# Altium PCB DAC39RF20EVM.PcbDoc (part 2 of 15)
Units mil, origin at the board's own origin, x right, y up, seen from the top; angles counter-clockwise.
Board outline 6200 x 2716.54 mil, 16 copper layers (Top Layer, L2 GND, L3 PWR, L4 GND, L5 PWR, L6 GND, L7 SIG, L8 GND, L9 GND, L10 SIG, L11 GND, L12 PWR, L13 GND, L14 PWR, L15 GND, Bottom Layer), stack 76.97 mil thick; 766 components, 495 nets, 3414 pads, 2373 vias.
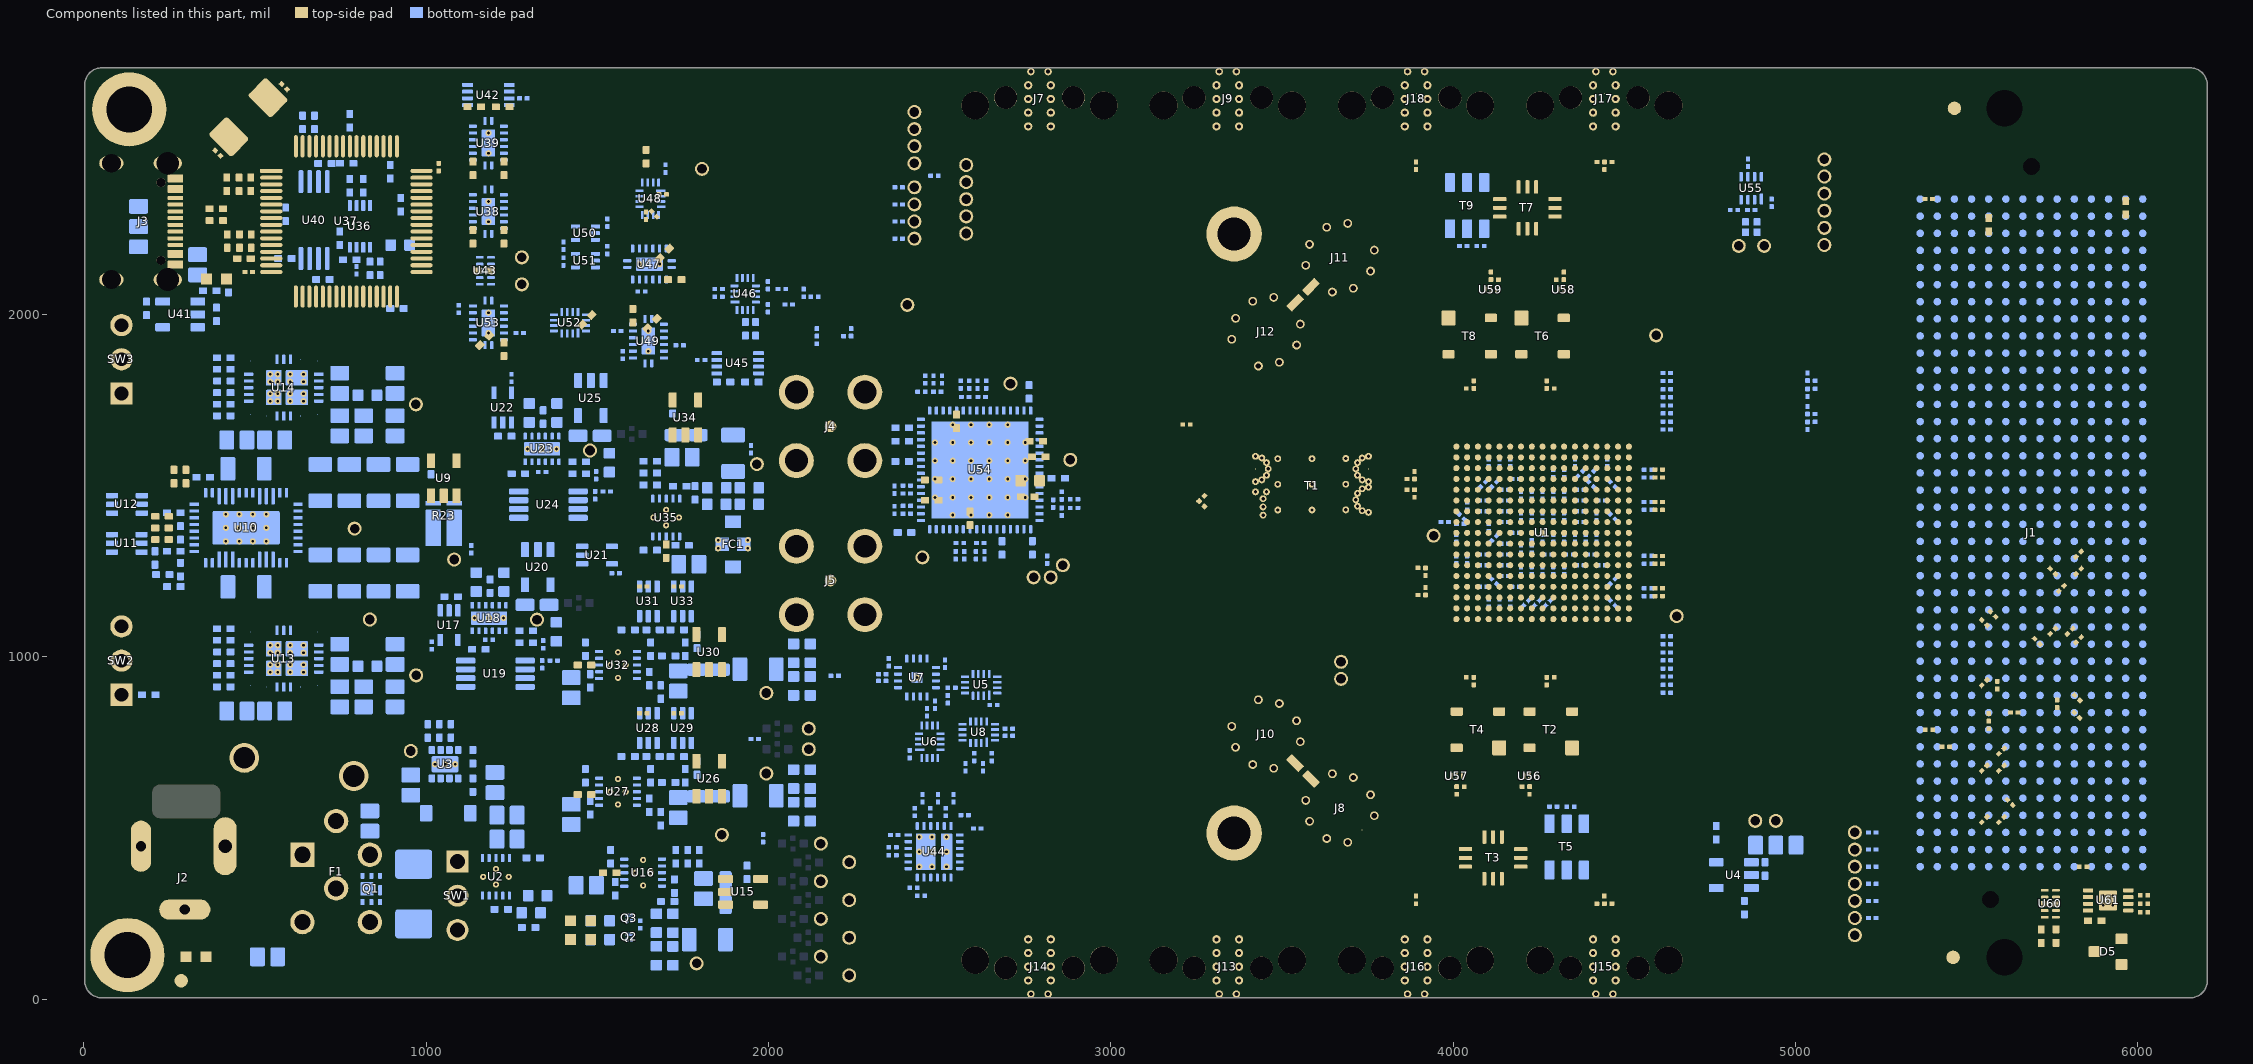
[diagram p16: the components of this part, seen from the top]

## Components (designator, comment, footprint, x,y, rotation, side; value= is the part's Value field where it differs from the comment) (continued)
C314 "GRM033Z71C104KE14D" 0201_cap 4150.76,1235.98 r0 bottom value="0.1 uF"
C315 "GRT155R71E104KE01J" 0402L_cap#1 5760.47,184.11 r90 top value="0.1 uF"
C316 "GRT155R71E104KE01J" 0402L_cap#1 5874.08,228.79 r180 top value="0.1 uF"
D1 "LTST-C191TGKT" LED_LTST-C190-Green 327.74,123.65 r0 top
D2 "SMBJ15CA" SMBJ15CA 963.6,306.98 r90 bottom
D3 "MBR130T1G" SOD-123 1064.36,543.16 r180 bottom
D4 "LTST-C191TGKT" LED_LTST-C190-Green 387.59,2103.8 r0 top
D5 "SDM40E20LC-7" SOT-323-DIO 5912.59,138.8 r180 top
D6 "LTST-C190KRKT" LED_LTST-C190-Red 1451.22,174.11 r180 top
D7 "LTST-C190KRKT" LED_LTST-C190-Red 1451.22,229.11 r180 top
F1 "BNX002-11" FIL_BNX002-11 737.07,323.38 r90 top
FB1 "BLE18PS080SN1D" 0603L 828.49,972.43 r0 bottom value=-
FB2 "BLE18PS080SN1D" 0603L 828.49,1763.95 r0 bottom value=-
FB3 "BLM31KN601SN1L" 1206L 1821.49,174.11 r180 bottom value=-
FB4 "BLM31KN601SN1L" 1206L 1969.67,593.85 r0 bottom value=-
FB5 "BLM31KN601SN1L" 1206L 1969.67,963.85 r0 bottom value=-
FB6 "BLM31KN601SN1L" 1206L 1896.28,1594.5 r270 bottom value=-
FB7 "NFZ15SG151SN11D" 0402L_cap#1 418.96,2214.36 r90 top value=-
FB8 "NFZ15SG151SN11D" 0402L_cap#1 417.59,2379.88 r270 top value=-
FC1 "dcp00001" NFM31PC 1896.28,1328.65 r270 bottom value=27uF
FID1 "Fiducial Mark" Fiducial10-20 284.47,53.8 r90 top
FID2 "Fiducial Mark" Fiducial10-20 5460.01,122.07 r90 top
FID3 "Fiducial Mark" Fiducial10-20 5464.01,2602.07 r90 top
H1 "CBTS130A" cbts130a 132.59,2598.8 r0 top locked
H3 "CBTS130A" cbts130a 127.59,128.8 r0 top
H5 "1797A" Keystone_1797B 3360,2235 r0 top
H6 "1797A" Keystone_1797B 3360,485 r0 top
J1 "ASP-184330-01" Samtec_ASP-184330-01 5689.01,1362.07 r90 bottom locked
J2 "RAPC722X" RAPC722X 167.02,446.8 r0 top
J3 "USB4105-GF-A" FP-USB4105-GF-A_CONN_USB_9MM58_7MM53-MFG 126.41,2271.61 r270 top
J4 "132134-15" FP-132134-15_CONN_SMA_JACK-MFG 2181.22,1672.88 r90 top
J5 "132134-15" FP-132134-15_CONN_SMA_JACK-MFG 2181.22,1222.88 r0 top
J7 "HK-LR-SR2(11)" HiRose-HK-LR-SR2-SWM1092-04A-MicroStirp-6mil-Female-Backdrill 2791.51,2720.34 r270 top
J8 "0853050232" Molex_0853050232 3584.5,643.16 r45 top
J9 "HK-LR-SR2(11)" HiRose-HK-LR-SR2-SWM1092-04A-MicroStirp-6mil-Female-Backdrill 3341.51,2720.34 r270 top
J10 "0853050232" Molex_0853050232 3538.14,689.52 r225 top
J11 "0853050232" Molex_0853050232 3584.45,2080.73 r135 top
J12 "0853050232" Molex_0853050232 3538.19,2034.47 r315 top
J13 "HK-LR-SR2(11)" HiRose-HK-LR-SR2-SWM1092-04A-MicroStirp-6mil-Female-Backdrill 3341.51,3.8 r90 top
J14 "HK-LR-SR2(11)" HiRose-HK-LR-SR2-SWM1092-04A-MicroStirp-6mil-Female-Backdrill 2791.51,3.8 r90 top
J15 "HK-LR-SR2(11)" HiRose-HK-LR-SR2-SWM1092-04A-MicroStirp-6mil-Female-Backdrill 4441.51,3.8 r90 top
J16 "HK-LR-SR2(11)" HiRose-HK-LR-SR2-SWM1092-04A-MicroStirp-6mil-Female-Backdrill 3891.51,3.8 r90 top
J17 "HK-LR-SR2(11)" HiRose-HK-LR-SR2-SWM1092-04A-MicroStirp-6mil-Female-Backdrill 4441.51,2720.34 r270 top
J18 "HK-LR-SR2(11)" HiRose-HK-LR-SR2-SWM1092-04A-MicroStirp-6mil-Female-Backdrill 3891.51,2720.34 r270 top
LBL1 "THT-14-423-10" Label_650x200 4941.3,816.41 r180 top
LOGO1 "CAUTION HOT SURFACE" IEC_HotSurface_Small 4777.61,1803.8 r0 top
Logo2 "FCC disclaimer" FCC_disclaimer 3657.85,1904.24 r180 bottom
Logo3 "ESD Overlay" ESD_Overlay_Small 4515,1760 r0 top
Logo4 "WEEE" WEEE_Minimum 1952.61,2423.8 r180 bottom
LOGO5 "CE Mark" CE_Mark_5mm 2895,2080 r180 bottom
Logo6 "Texas Instruments" TI_Stacked_Overlay_Small_Vertical 5642.61,1848.8 r270 top
Logo7 "FDL Logo" FDL_Small 1176.93,870.94 r0 top
Logo8 "Texas Instruments" TI_Symbol_Overlay_Medium 2588.66,694.83 r0 top
PP1 "Probe Point" ProbePoint_TH_40mil 955.09,724.79 r0 top
PP2 "Probe Point" ProbePoint_TH_40mil 4942.16,520.76 r90 top
PP3 "Probe Point" ProbePoint_TH_40mil 4882.16,520.76 r90 top
PP4 "Probe Point" ProbePoint_TH_40mil 2449.61,1290.17 r0 top
PP5 "Probe Point" ProbePoint_TH_40mil 5084.05,2202.9 r0 top
PP6 "Probe Point" ProbePoint_TH_40mil 5173.01,186.94 r0 top
PP7 "Probe Point" ProbePoint_TH_40mil 1805.78,2425.07 r0 top
PP8 "Probe Point" ProbePoint_TH_40mil 1863.97,479.87 r0 top
PP9 "Probe Point" ProbePoint_TH_40mil 835.49,1109 r0 top
PP10 "Probe Point" ProbePoint_TH_40mil 790.91,1374.53 r0 bottom
PP11 "Probe Point" ProbePoint_TH_40mil 1081.93,1284.07 r0 bottom
PP12 "Probe Point" ProbePoint_TH_40mil 970.86,945.8 r0 top
PP13 "Probe Point" ProbePoint_TH_40mil 970.09,1737.32 r0 top
PP14 "Probe Point" ProbePoint_TH_40mil 1789.86,104.37 r180 bottom
PP15 "Probe Point" ProbePoint_TH_40mil 2152.86,454.37 r0 top
PP16 "Probe Point" ProbePoint_TH_40mil 2152.86,124.37 r0 top
PP17 "Probe Point" ProbePoint_TH_40mil 2235.74,69.37 r0 top
PP18 "Probe Point" ProbePoint_TH_40mil 2152.86,234.37 r0 top
PP19 "Probe Point" ProbePoint_TH_40mil 2235.74,289.37 r0 top
PP20 "Probe Point" ProbePoint_TH_40mil 2152.86,344.37 r0 top
PP21 "Probe Point" ProbePoint_TH_40mil 2235.74,400.14 r0 top
PP22 "Probe Point" ProbePoint_TH_40mil 2235.74,179.37 r0 top
PP23 "Probe Point" ProbePoint_TH_40mil 1323.69,1108.44 r270 bottom
PP24 "Probe Point" ProbePoint_TH_40mil 1478.5,1602.46 r90 top
PP25 "Probe Point" ProbePoint_TH_40mil 1993.58,659.19 r180 bottom
PP26 "Probe Point" ProbePoint_TH_40mil 2117.52,730.04 r270 bottom
PP27 "Probe Point" ProbePoint_TH_40mil 2117.52,790.04 r180 bottom
PP28 "Probe Point" ProbePoint_TH_40mil 1993.58,894.19 r0 bottom
PP29 "Probe Point" ProbePoint_TH_40mil 1966.02,1562.87 r270 bottom
PP30 "Probe Point" ProbePoint_TH_40mil 1279.44,2088.03 r0 top
PP31 "Probe Point" ProbePoint_TH_40mil 1279.44,2166.77 r0 top
PP32 "Probe Point" ProbePoint_TH_40mil 2824.32,1232.14 r0 top
PP33 "Probe Point" ProbePoint_TH_40mil 2774.32,1232.14 r0 top
PP34 "Probe Point" ProbePoint_TH_40mil 2706.77,1798.03 r0 top
PP35 "Probe Point" ProbePoint_TH_40mil 2859.68,1267.5 r0 top
PP36 "Probe Point" ProbePoint_TH_40mil 5084.05,2402.9 r0 top
PP37 "Probe Point" ProbePoint_TH_40mil 5084.05,2352.9 r0 top
PP38 "Probe Point" ProbePoint_TH_40mil 5084.05,2452.9 r0 top
PP39 "Probe Point" ProbePoint_TH_40mil 5084.05,2252.9 r0 top
PP40 "Probe Point" ProbePoint_TH_40mil 2405.59,2027.82 r90 top
PP41 "Probe Point" ProbePoint_TH_40mil 5084.05,2302.9 r0 top
PP42 "Probe Point" ProbePoint_TH_40mil 2426.12,2371.38 r0 top
PP43 "Probe Point" ProbePoint_TH_40mil 2426.12,2221.38 r0 top
PP44 "Probe Point" ProbePoint_TH_40mil 2426.12,2321.38 r0 top
PP45 "Probe Point" ProbePoint_TH_40mil 2426.12,2271.38 r0 top
PP46 "Probe Point" ProbePoint_TH_40mil 2881.41,1575.36 r180 bottom
PP47 "Probe Point" ProbePoint_TH_40mil 3672.29,935.47 r0 top
PP48 "Probe Point" ProbePoint_TH_40mil 5173.01,486.94 r180 top
PP49 "Probe Point" ProbePoint_TH_40mil 5173.01,236.94 r180 top
PP50 "Probe Point" ProbePoint_TH_40mil 5173.01,286.94 r180 top
PP51 "Probe Point" ProbePoint_TH_40mil 5173.01,336.94 r180 top
PP52 "Probe Point" ProbePoint_TH_40mil 5173.01,386.94 r180 top
PP53 "Probe Point" ProbePoint_TH_40mil 5173.01,436.94 r180 top
PP54 "Probe Point" ProbePoint_TH_40mil 3672.29,985.47 r0 top
PP55 "Probe Point" ProbePoint_TH_40mil 4908.08,2200.21 r90 top
PP56 "Probe Point" ProbePoint_TH_40mil 2577.51,2436.45 r0 top
PP57 "Probe Point" ProbePoint_TH_40mil 3942.61,1353.8 r0 top
PP58 "Probe Point" ProbePoint_TH_40mil 4592.61,1938.8 r0 top
PP59 "Probe Point" ProbePoint_TH_40mil 2577.51,2386.45 r0 top
PP60 "Probe Point" ProbePoint_TH_40mil 4834.03,2200.21 r90 top
PP61 "Probe Point" ProbePoint_TH_40mil 2577.51,2336.45 r0 top
PP62 "Probe Point" ProbePoint_TH_40mil 4652.61,1118.8 r0 top
PP63 "Probe Point" ProbePoint_TH_40mil 2577.51,2236.45 r0 top
PP64 "Probe Point" ProbePoint_TH_40mil 2577.51,2286.45 r0 top
PP65 "Probe Point" ProbePoint_TH_40mil 2426.12,2591.38 r0 top
PP66 "Probe Point" ProbePoint_TH_40mil 2426.12,2491.38 r0 top
PP67 "Probe Point" ProbePoint_TH_40mil 2426.12,2441.38 r0 top
PP68 "Probe Point" ProbePoint_TH_40mil 2426.12,2541.38 r0 top
Q1 "CSD15571Q2" DQK0006C 839.83,321.96 r270 bottom
Q2 "CSD25480F3" YJM0003A 1592.76,181 r90 bottom value=-20V
Q3 "CSD25480F3" YJM0003A 1592.76,236 r90 bottom value=-20V
R1 "ERJ-2RKF1004X" 0402L#1 1219.35,262.2 r180 bottom value="1 MΩ"
R2 "ERJ-2RKF7682X" 0402L#1 1312.87,412.44 r180 bottom value="76.8 kΩ"
R3 "ERJ-6ENF4701V" 0805L 536.79,123.65 r180 bottom value="4.7 kΩ"
R4 "ERJ-2RKF1623X" 0402L#1 1299.22,209.42 r180 bottom value="162 kΩ"
R5 "ERJ-2RKF1002X" 0402L#1 1071.89,783.31 r90 bottom value="10 kΩ"
R6 "ERJ-6GEY0R00V" 0805L 4912.63,449.74 r180 bottom value="0 Ω"
R7 "ERJ-6GEY0R00V" 0805L 4971.69,449.74 r180 bottom value="0 Ω"
R8 "ERJ-2RKF1002X" 0402L#1 1136.48,625.27 r270 bottom value="10 kΩ"
R9 "ERJ-2RKF1002X" 0402L#1 4850.49,267.45 r270 bottom value="10 kΩ"
R10 "ERA-2AEB3742X" 0402L#1 1038.3,783.31 r90 bottom value="37.4 kΩ"
R11 "ERJ-2RKF1202X" 0402L#1 1004.7,783.31 r270 bottom value="12 kΩ"
R12 "ERJ-1GNF1000C" 0201#1 2534.65,909.89 r180 bottom value="100 Ω"
R13 "ERJ-1GNF1002C" 0201#1 2626.71,677.07 r270 bottom value="10 kΩ"
R14 "ERJ-1GNF1002C" 0201#1 2600.96,707.07 r270 bottom value="10 kΩ"
R15 "ERJ-1GNF1002C" 0201#1 2575.21,677.07 r270 bottom value="10 kΩ"
R16 "ERJ-1GNF1000C" 0201#1 2463.04,838.27 r90 bottom value="100 Ω"
R17 "ERJ-1GNF1002C" 0201#1 2351.39,983.97 r90 bottom value="10 kΩ"
R18 "ERJ-1GNF1002C" 0201#1 2515.63,979.97 r90 bottom value="10 kΩ"
R19 "ERJ-1GNF1002C" 0201#1 2652.46,707.07 r270 bottom value="10 kΩ"
R20 "ERJ-2RKF1002X" 0402L#1 349.09,1524.51 r180 bottom value="10 kΩ"
R21 "ERJ-2RKF1003X" 0402L#1 298.22,1526.56 r90 top value="100 kΩ"
R22 "ERJ-1GNF1000C" 0201#1 1131.81,1314.23 r270 bottom value="100 Ω"
R23 "KRL3216T4A-M-R005-F-T1" FP-KRL3216T4A-M-R005-F-T1_1206-MFG 1051.42,1389.39 r180 bottom
R24 "ERA-2APB2551X" 0402L#1 228.46,1342.34 r180 top value="2.55 kΩ"
R25 "ERJ-2RKF1402X" 0402L#1 263.22,1526.57 r270 top value="14 kΩ"
R26 "ERJ-2RKF1002X" 0402L#1 282.52,1254.54 r90 bottom value="10 kΩ"
R27 "ERJ-2RKF1072X" 0402L#1 262.83,1205.23 r0 bottom value="10.7 kΩ"
R28 "ERJ-2RKF1742X" 0402L#1 230.83,1240.23 r0 bottom value="17.4 kΩ"
R29 "ERA-2ARB222X" 0402L#1 228.46,1376.34 r0 top value="2.2 kΩ"
R30 "ERA-2ARB1692X" 0402L#1 282.52,1362.03 r90 bottom value="16.9 kΩ"
R31 "ERJ-PA2F1004X" 0402L#1 207.78,1288.66 r270 bottom value="1 MΩ"
R32 "ERA-2APB223X" 0402L#1 228.46,1410.34 r0 top value="22 kΩ"
R33 "ERJ-2RKF1002X" 0402L#1 409.06,912.11 r180 bottom value="10 kΩ"
R34 "ERJ-2RKF1002X" 0402L#1 409.06,1082.11 r180 bottom value="10 kΩ"
R35 "ERA-2AEB9311X" 0402L#1 409.06,980.11 r180 bottom value="9.31 kΩ"
R36 "ERJ-2RKF8062X" 0402L#1 409.06,1048.11 r0 bottom value="80.6 kΩ"
R37 "ERA-2AEB4871X" 0402L#1 409.06,1014.11 r0 bottom value="4.87 kΩ"
R38 "ERJ-2RKF1002X" 0402L#1 409.06,1703.64 r180 bottom value="10 kΩ"
R39 "ERJ-2RKF1002X" 0402L#1 409.06,1873.64 r180 bottom value="10 kΩ"
R40 "ERA-2ARB1822X" 0402L#1 409.06,1771.64 r180 bottom value="18.2 kΩ"
R41 "ERJ-2RKF8062X" 0402L#1 409.06,1839.64 r0 bottom value="80.6 kΩ"
R42 "ERA-2AEB4871X" 0402L#1 409.06,1805.64 r0 bottom value="4.87 kΩ"
R43 "ERJ-1GNF1000C" 0201#1 1984.17,470.07 r90 bottom value="100 Ω"
R44 "ERJ-2RKF1002X" 0402L#1 1538.65,415.77 r90 bottom value="10 kΩ"
R45 "ERJ-2RKF1002X" 0402L#1 1535.78,369.31 r180 top value="10 kΩ"
R46 "CSS0603FT10L0" CCS0603FLxLxx 1874.64,310.84 r270 bottom value="10 mΩ"
R47 "ERA-2AEB8872X" 0402L#1 1725.29,329.94 r90 bottom value="88.7 kΩ"
R48 "ERA-2AEB1242X" 0402L#1 1705.6,285.25 r0 bottom value="12.4 kΩ"
R49 "ERJ-U2RD1202X" 0402L#2 1763.89,415.77 r270 bottom value="12 kΩ"
R50 "ERJ-U020R00X" 0402L#1 1797.89,415.77 r90 bottom value="0 Ω"
R51 "ERJ-H2RF1002X" 0402L#1 1072.83,1175.76 r180 bottom value="10 kΩ"
R52 "CSS0603FT5L00" CCS0603FLxLxx 1324.22,1151.61 r0 bottom value="5 mΩ"
R53 "ERJ-2RKF2552X" 0402L#1 1292.6,1075.81 r0 bottom value="25.5 kΩ"
R54 "ERJ-U01F1002C" 0201#1 1338.79,977.85 r90 bottom value="10 kΩ"
R55 "ERJ-H2RF1002X" 0402L#1 1154.17,1021.81 r180 bottom value="10 kΩ"
R56 "ERJ-2RKF4992X" 0402L#1 1292.6,1040.81 r180 bottom value="49.9 kΩ"
R57 "ERJ-U01F1002C" 0201#1 1341.61,1036.1 r270 bottom value="10 kΩ"
R58 "ERJ-1GNF1000C" 0201#1 1372.81,988.88 r0 bottom value="100 Ω"
R59 "ERJ-H2RF1002X" 0402L#1 1229.62,1644.63 r180 bottom value="10 kΩ"
R60 "CSS0603FT5L00" CCS0603FLxLxx 1479.03,1645.63 r0 bottom value="5 mΩ"
R61 "ERJ-2RKF2552X" 0402L#1 1447.41,1569.83 r0 bottom value="25.5 kΩ"
R62 "ERJ-U01F1002C" 0201#1 1493.6,1471.87 r90 bottom value="10 kΩ"
R63 "ERJ-H2RF1002X" 0402L#1 1269.62,1534.83 r0 bottom value="10 kΩ"
R64 "ERJ-2RKF4992X" 0402L#1 1447.41,1534.83 r180 bottom value="49.9 kΩ"
R65 "ERJ-U01F1002C" 0201#1 1496.43,1530.11 r270 bottom value="10 kΩ"
R66 "ERJ-1GNF1000C" 0201#1 1527.62,1482.89 r0 bottom value="100 Ω"
R67 "ERJ-1GNF1000C" 0201#1 1959.96,759.86 r180 bottom value="100 Ω"
R68 "ERJ-2RKF1002X" 0402L#1 1465.29,652.31 r90 bottom value="10 kΩ"
R69 "ERJ-2RKF1002X" 0402L#1 1462.42,597.86 r180 top value="10 kΩ"
R70 "CSS0603FT5L00" CCS0603FLxLxx 1824.6,592.47 r0 bottom value="5 mΩ"
R71 "ERA-2AEB8872X" 0402L#1 1651.92,566.49 r90 bottom value="88.7 kΩ"
R72 "ERA-2ARB5231X" 0402L#1 1662.7,708.57 r180 bottom value="5.23 kΩ"
R73 "ERA-2AEB3322X" 0402L#1 1685.52,527.12 r90 bottom value="33.2 kΩ"
R74 "ERJ-PA2F1004X" 0402L#1 1589.87,708.57 r180 bottom value="1 MΩ"
R75 "ERA-2AEB6651X" 0402L#1 1708.21,632.63 r180 bottom value="6.65 kΩ"
R76 "ERJ-U020R00X" 0402L#1 1756.89,652.31 r270 bottom value="0 Ω"
R77 "ERA-2AEB8872X" 0402L#1 1733.21,708.57 r180 bottom value="88.7 kΩ"
R78 "ERJ-1GNF1000C" 0201#1 2193.3,944.55 r0 bottom value="100 Ω"
R79 "ERJ-2RKF1002X" 0402L#1 1465.29,1022.31 r90 bottom value="10 kΩ"
R80 "ERA-2ARB5231X" 0402L#1 1662.7,1078.57 r180 bottom value="5.23 kΩ"
R81 "ERJ-PA2F1004X" 0402L#1 1589.87,1078.57 r180 bottom value="1 MΩ"
R82 "ERJ-2RKF1002X" 0402L#1 1462.42,975.86 r180 top value="10 kΩ"
R83 "CSS0603FT10L0" CCS0603FLxLxx 1824.6,962.47 r0 bottom value="10 mΩ"
R84 "ERA-2AEB8872X" 0402L#1 1651.92,936.49 r90 bottom value="88.7 kΩ"
R85 "ERA-2AEB8872X" 0402L#1 1733.21,1078.57 r180 bottom value="88.7 kΩ"
R86 "ERA-2AEB3322X" 0402L#1 1685.52,897.12 r90 bottom value="33.2 kΩ"
R87 "ERA-2AEB5361X" 0402L#1 1708.21,1002.63 r180 bottom value="5.36 kΩ"
R88 "ERJ-U020R00X" 0402L#1 1756.89,1022.31 r270 bottom value="0 Ω"
R89 "ERJ-1GNF1000C" 0201#1 1948.93,1606.23 r90 bottom value="100 Ω"
R90 "ERJ-2RKF1002X" 0402L#1 1654.63,1311.67 r180 bottom value="10 kΩ"
R91 "ERJ-2RKF1002X" 0402L#1 1701.09,1308.8 r270 top value="10 kΩ"
R92 "CSS0603FT10L0" CCS0603FLxLxx 1759.55,1647.65 r0 bottom value="10 mΩ"
R93 "ERJ-2RKF1743X" 0402L#1 1740.46,1498.3 r180 bottom value="174 kΩ"
R94 "ERA-2AEB1242X" 0402L#1 1785.14,1478.62 r90 bottom value="12.4 kΩ"
R95 "ERA-2AEB223X" 0402L#2 1654.63,1536.9 r0 bottom value="22 kΩ"
R96 "ERJ-U020R00X" 0402L#1 1654.63,1570.9 r180 bottom value="0 Ω"
R97 "ERJ-2RKF1002X" 0402L#1 776.93,2160.02 r180 bottom value="10 kΩ"
R98 "ERJ-2RKF4701X" 0402L#1 816.3,2375.75 r270 bottom value="4.7 kΩ"
R99 "ERJ-1GN0R00C" 0201#1 481.57,2123.97 r180 top value="0 Ω"
R100 "ERJ-2RKF1002X" 0402L#1 776.93,2375.75 r90 bottom value="10 kΩ"
R101 "ERJ-2RKF4701X" 0402L#1 865.71,2134.37 r270 bottom value="4.7 kΩ"
R102 "ERJ-1GN0R00C" 0201#1 796.61,2128.99 r90 bottom value="0 Ω"
R103 "ERJ-2RKF1000X" 0402L#1 835.98,2134.37 r270 bottom value="100 Ω"
R104 "ERJ-6GEY0R00V" 0805L 332.41,2145.08 r270 bottom value="0 Ω"
R105 "ERJ-2GEJ100X" 0402L#1 467.91,2163.02 r180 top value="10 Ω"
R106 "ERJ-2GEJ100X" 0402L#1 387.44,2308.54 r0 top value="10 Ω"
R107 "ERJ-1GN0R00C" 0201#1 1036.57,2430.27 r90 top value="0 Ω"
R108 "ERJ-2GEJ222X" 0402L#1 422.59,2084.11 r90 bottom value="2.2 kΩ"
R109 "ERJ-2GEJ100X" 0402L#1 387.44,2274.05 r0 top value="10 Ω"
R110 "ERJ-2GEJ123X" 0402L#1 589.59,2292.1 r90 bottom value="12 kΩ"
R111 "ERJ-2RKF1002X" 0402L#1 673.81,2560.78 r90 bottom value="10 kΩ"
R112 "ERJ-2RKF1002X" 0402L#1 767.57,2441.3 r0 bottom value="10 kΩ"
R113 "ERJ-2RKF1002X" 0402L#1 639.13,2560.78 r90 bottom value="10 kΩ"
R114 "ERJ-2GEJ222X" 0402L#1 704.13,2440.97 r180 bottom value="2.2 kΩ"
R115 "ERJ-6GEY0R00V" 0805L 159.94,2227.07 r270 bottom value="0 Ω"
R116 "ERJ-6GEY0R00V" 0805L 159.94,2286.13 r270 bottom value="0 Ω"
R117 "ERJ-2GEJ222X" 0402L#1 387.33,1999.98 r90 bottom value="2.2 kΩ"
R118 "ERJ-2RKF1002X" 0402L#1 189.76,888.8 r0 bottom value="10 kΩ"
R119 "ERJ-1GNF4701C" 0201#1 2426.92,546.75 r90 bottom value="4.7 kΩ"
R120 "ERJ-1GNF4701C" 0201#1 2449.61,586.75 r90 bottom value="4.7 kΩ"
R121 "ERJ-1GNF4701C" 0201#1 2472.29,546.75 r90 bottom value="4.7 kΩ"
R122 "ERJ-1GNF4701C" 0201#1 2494.98,586.75 r90 bottom value="4.7 kΩ"
R123 "ERJ-1GNF4701C" 0201#1 2517.66,546.75 r90 bottom value="4.7 kΩ"
R124 "ERJ-1GNF4701C" 0201#1 2540.35,586.75 r90 bottom value="4.7 kΩ"
R125 "ERJ-1GNF4701C" 0201#1 2572.89,537.41 r180 bottom value="4.7 kΩ"
R126 "ERJ-1GNF4701C" 0201#1 2610.05,498.34 r0 bottom value="4.7 kΩ"
R127 "ERJ-1GNF4701C" 0201#1 2367.32,479.64 r180 bottom value="4.7 kΩ"
R128 "ERJ-1GNF1002C" 0201#1 2362.32,420.59 r180 bottom value="10 kΩ"
R129 "ERJ-1GNF1002C" 0201#1 2445.45,302.13 r180 bottom value="10 kΩ"
R130 "ERJ-1GNF1002C" 0201#1 2362.32,443.59 r0 bottom value="10 kΩ"
R131 "ERJ-1GNF1002C" 0201#1 2423.4,325.13 r180 bottom value="10 kΩ"
R132 "ERJ-1GNF1002C" 0201#1 1998.15,2085.45 r270 bottom value="10 kΩ"
R133 "ERJ-1GNF1002C" 0201#1 2102.61,2062.85 r270 bottom value="10 kΩ"
R134 "ERJ-1GNF1002C" 0201#1 1998.15,2018.21 r90 bottom value="10 kΩ"
R135 "ERJ-1GN0R00C" 0201#1 2484.56,2404.99 r0 bottom value="0 Ω"
R136 "ERJ-1GN0R00C" 0201#1 1854.14,2051.83 r180 bottom value="0 Ω"
R137 "ERJ-1GN0R00C" 0201#1 1854.14,2074.43 r180 bottom value="0 Ω"
R138 "ERJ-1GNF1002C" 0201#1 2813.86,1283.73 r270 bottom value="10 kΩ"
R139 "ERJ-1GNF1002C" 0201#1 1740.41,1909.86 r180 bottom value="10 kΩ"
R140 "ERJ-1GNF1002C" 0201#1 1628.99,2066.83 r0 bottom value="10 kΩ"
R141 "ERJ-1GNF49R9C" 0201#1 1698.86,2426.02 r270 bottom value="49.9 Ω"
R142 "ERJ-1GNF1002C" 0201#1 1690.71,2350.62 r180 top value="10 kΩ"
R143 "ERJ-1GNF1002C" 0201#1 1666.06,2293.3 r135 top value="10 kΩ"
R144 "ERJ-1GNF1002C" 0201#1 1642.36,2288.29 r90 top value="10 kΩ"
R145 "ERJ-1GNF1002C" 0201#1 1529.29,2267.97 r270 bottom value="10 kΩ"
R146 "ERJ-1GNF49R9C" 0201#1 1401.02,2200.69 r90 bottom value="49.9 Ω"
R147 "ERJ-1GNF49R9C" 0201#1 1557.81,1951.73 r180 bottom value="49.9 Ω"
R148 "ERJ-1GNF1002C" 0201#1 1573.83,1881.65 r270 bottom value="10 kΩ"
R149 "ERJ-1GNF1002C" 0201#1 1529.29,2187.97 r270 bottom value="10 kΩ"
R150 "ERJ-1GNF49R9C" 0201#1 1401.02,2154.47 r270 bottom value="49.9 Ω"
R151 "ERJ-1GNF1002C" 0201#1 2380.1,2271.38 r0 bottom value="10 kΩ"
R152 "ERJ-1GNF1002C" 0201#1 1095.32,2015.9 r270 bottom value="10 kΩ"
R153 "ERJ-1GNF49R9C" 0201#1 1273.15,1945.82 r0 bottom value="49.9 Ω"
R154 "ERJ-1GNF1002C" 0201#1 2380.1,2371.38 r180 bottom value="10 kΩ"
R155 "ERJ-1GNF1002C" 0201#1 2380.1,2221.38 r180 bottom value="10 kΩ"
R156 "ERJ-1GNF1002C" 0201#1 2380.1,2321.38 r180 bottom value="10 kΩ"
R157 "ERJ-1GNF49R9C" 0201#1 2367.91,1487.96 r270 bottom value="49.9 Ω"
R158 "ERJ-U01J561C" 0201#1 2831.41,1447.4 r270 bottom value="560 Ω"
R159 "ERJ-1GNF2400C" 0201#1 2856.41,1470.95 r270 bottom value="240 Ω"
R160 "ERJ-1GNF2400C" 0201#1 2856.41,1423.86 r90 bottom value="240 Ω"
R161 "ERJ-1GNF49R9C" 0201#1 2367.91,1428.9 r270 bottom value="49.9 Ω"
R162 "ERJ-U01J561C" 0201#1 2618.18,1332.6 r180 bottom value="560 Ω"
R163 "ERJ-U01J561C" 0201#1 2559.13,1332.6 r180 bottom value="560 Ω"
R164 "ERJ-U01J561C" 0201#1 2574.21,1759.06 r0 bottom value="560 Ω"
R165 "ERJ-U01J561C" 0201#1 2622.4,1759.06 r180 bottom value="560 Ω"
R166 "ERJ-1GNF2400C" 0201#1 2446.64,1774.06 r0 bottom value="240 Ω"
R167 "ERJ-1GNF2400C" 0201#1 2492.87,1774.06 r180 bottom value="240 Ω"
R168 "ERJ-1GNF49R9C" 0201#1 2506.85,1810.08 r90 bottom value="49.9 Ω"
R169 "ERJ-H2RF1002X" 0402L#1 2781.73,1629.49 r0 top value="10 kΩ"
R170 "ERJ-H2RF1002X" 0402L#1 2788.96,1584.53 r0 top value="10 kΩ"
R171 "ERJ-1GN0R00C" 0201#1 3919.03,1191.65 r90 top value="0 Ω"
R172 "ERJ-1GN0R00C" 0201#1 3908,1180.63 r180 top value="0 Ω"
R173 "ERJ-1GN0R00C" 0201#1 3919.03,1248.82 r270 top value="0 Ω"
R174 "ERJ-1GN0R00C" 0201#1 3908,1259.85 r180 top value="0 Ω"
R175 "ERJ-1GNF3601C" 0201#1 4009.03,1346.22 r270 bottom value="3.6 kΩ"
R176 "ERJ-U01F1002C" 0201#1 4860.74,2443.09 r90 bottom value="10 kΩ"
R177 "ERJ-U01F1002C" 0201#1 4820.03,2305.14 r180 bottom value="10 kΩ"
R178 "ERJ-1GNF1000C" 0201L#2 4887.61,2255.18 r90 bottom value="100 Ω"
R179 "ERJ-1GNF1001C" 0201#1 3975,1393.46 r180 bottom value="1 kΩ"
R180 "ERJ-1GNF1000C" 0201L#2 4853.56,2255.18 r90 bottom value="100 Ω"
R181 "ERJ-1GN0R00C" 0201#2 4434.22,1267.48 r0 bottom value="0 Ω"
R182 "ERJ-1GN0R00C" 0201#1 4284.04,940 r0 top value="0 Ω"
R183 "ERJ-1GN0R00C" 0201#1 4273.02,928.98 r270 top value="0 Ω"
R184 "ERJ-1GN0R00C" 0201#2 4441.51,289.82 r90 top value="0 Ω"
R185 "ERJ-1GN0R00C" 0201#2 3891.51,289.82 r270 top value="0 Ω"
R186 "ERJ-1GN0R00C" 0201#1 4060,928.98 r270 top value="0 Ω"
R187 "ERJ-1GN0R00C" 0201#1 4048.98,940 r180 top value="0 Ω"
R188 "ERJ-1GN0R00C" 0201#1 4284.04,1783.94 r0 top value="0 Ω"
R189 "ERJ-1GN0R00C" 0201#1 4273.02,1794.96 r90 top value="0 Ω"
R190 "ERJ-1GN0R00C" 0201#1 4441.51,2434.11 r270 top value="0 Ω"
R191 "ERJ-1GN0R00C" 0201#1 3891.51,2434.11 r90 top value="0 Ω"
R192 "ERJ-1GN0R00C" 0201#1 4060,1794.96 r90 top value="0 Ω"
R193 "ERJ-1GN0R00C" 0201#1 4048.98,1783.94 r180 top value="0 Ω"
R194 "ERJ-2RKF1002X" 0402L#1 5717.59,184.11 r90 top value="10 kΩ"
R195 "ERJ-1GNJ103C" 0201#1 6017.67,253.79 r180 top value="10 kΩ"
R196 "ERJ-1GNJ103C" 0201#1 6017.67,278.48 r180 top value="10 kΩ"
R197 "ERJ-1GNJ103C" 0201#1 6017.67,303.16 r180 top value="10 kΩ"
R198 "ERJ-1GN0R00C" 0201#1 5839.7,387.07 r0 top value="0 Ω"
R199 "ERJ-1GN0R00C" 0201#1 5826.51,1299.57 r225 top value="0 Ω"
R200 "ERJ-1GN0R00C" 0201#1 5751.51,1249.57 r315 top value="0 Ω"
R201 "ERJ-1GN0R00C" 0201#1 5826.51,1249.57 r225 top value="0 Ω"
R202 "ERJ-1GN0R00C" 0201#1 5776.51,1199.57 r225 top value="0 Ω"
R203 "ERJ-1GN0R00C" 0201#1 5751.31,1074.77 r45 top value="0 Ω"
R204 "ERJ-1GN0R00C" 0201#1 5801.51,1074.57 r45 top value="0 Ω"
R205 "ERJ-1GN0R00C" 0201#1 5706.22,1044.86 r315 top value="0 Ω"
R206 "ERJ-1GN0R00C" 0201#1 5826.51,1049.57 r225 top value="0 Ω"
R207 "ERJ-1GN0R00C" 0201#1 5764.01,862.76 r90 top value="0 Ω"
R208 "ERJ-1GN0R00C" 0201#1 5822.78,880.25 r135 top value="0 Ω"
R209 "ERJ-1GN0R00C" 0201#1 5821.81,829.27 r135 top value="0 Ω"
R210 "ERJ-1GN0R00C" 0201#1 1802.96,1867.08 r180 bottom value="0 Ω"
R211 "ERJ-1GN0R00C" 0201#1 1283.89,2631.1 r0 bottom value="0 Ω"
R212 "ERJ-1GN0R00C" 0201#1 2039.18,2074.43 r0 bottom value="0 Ω"
R213 "ERJ-1GN0R00C" 0201#1 2134.18,2051.83 r0 bottom value="0 Ω"
R214 "ERJ-1GN0R00C" 0201#1 2059.18,2029.23 r0 bottom value="0 Ω"
R215 "ERJ-1GN0R00C" 0201#1 5638.94,837.07 r180 top value="0 Ω"
R216 "ERJ-1GN0R00C" 0201#1 5601.51,724.57 r45 top value="0 Ω"
R217 "ERJ-1GN0R00C" 0201#1 5601.51,674.57 r45 top value="0 Ω"
R218 "ERJ-1GN0R00C" 0201#1 5626.51,574.57 r135 top value="0 Ω"
R219 "ERJ-1GN0R00C" 0201#1 5601.51,524.57 r45 top value="0 Ω"
R220 "ERJ-2RKF1000X" 0402L#1 5564.01,2262.07 r90 top value="100 Ω"
R221 "ERJ-1GN0R00C" 0201#1 5576.51,1124.57 r135 top value="0 Ω"
R222 "ERJ-1GN0R00C" 0201#1 5551.51,1099.57 r315 top value="0 Ω"
R223 "ERJ-1GN0R00C" 0201#1 5589.01,917.2 r90 top value="0 Ω"
R224 "ERJ-1GN0R00C" 0201#1 5551.51,924.57 r45 top value="0 Ω"
R225 "ERJ-1GN0R00C" 0201#1 5564.01,823.09 r90 top value="0 Ω"
R226 "ERJ-1GN0R00C" 0201#1 5564.01,801.04 r270 top value="0 Ω"
R227 "ERJ-1GN0R00C" 0201#1 5551.51,674.57 r45 top value="0 Ω"
R228 "ERJ-1GN0R00C" 0201#1 5551.51,524.57 r45 top value="0 Ω"
R229 "ERJ-2RKF1000X" 0402L#1 5964.01,2312.07 r90 top value="100 Ω"
R230 "ERJ-1GN0R00C" 0201#1 5389.01,2337.07 r0 top value="0 Ω"
R231 "ERJ-1GN0R00C" 0201#1 5389.7,787.07 r0 top value="0 Ω"
R232 "ERJ-1GN0R00C" 0201#1 5439.01,737.07 r180 top value="0 Ω"
R233 "ERJ-1GN0R00C" 0201#1 5035.01,1720.2 r270 bottom value="0 Ω"
R234 "ERJ-1GN0R00C" 0201#1 5046.04,1709.18 r180 bottom value="0 Ω"
R235 "ERJ-3GEYJ331V" 0603L 1508.31,174.11 r0 bottom value="330 Ω"
R236 "ERJ-3GEYJ331V" 0603L 1508.31,229.11 r0 bottom value="330 Ω"
R237 "ERJ-1GN0R00C" 0201#1 5035.01,1675.16 r90 bottom value="0 Ω"
R238 "ERJ-1GN0R00C" 0201#1 5046.04,1686.18 r180 bottom value="0 Ω"
R239 "ERJ-1GN0R00C" 0201#1 5035.01,1818.11 r270 bottom value="0 Ω"
R240 "ERJ-1GN0R00C" 0201#1 5046.04,1806.42 r180 bottom value="0 Ω"
R241 "ERJ-1GN0R00C" 0201#1 5035.01,1771.06 r90 bottom value="0 Ω"
R242 "ERJ-1GN0R00C" 0201#1 5046.04,1782.75 r180 bottom value="0 Ω"
R243 "ERJ-1GN0R00C" 0201#1 5224.03,486.94 r180 bottom value="0 Ω"
R244 "ERJ-1GN0R00C" 0201#1 5224.03,236.94 r180 bottom value="0 Ω"
R245 "ERJ-1GN0R00C" 0201#1 5224.03,286.94 r180 bottom value="0 Ω"
R246 "ERJ-1GN0R00C" 0201#1 5224.03,336.94 r180 bottom value="0 Ω"
R247 "ERJ-1GN0R00C" 0201#1 5224.03,386.94 r180 bottom value="0 Ω"
R248 "ERJ-1GN0R00C" 0201#1 5224.03,436.94 r180 bottom value="0 Ω"
R249 "ERJ-1GN0R00C" 0201#1 1625.52,218.17 r270 bottom value="0 Ω"
R250 "ERJ-1GN0R00C" 0201#1 2241.26,1947.58 r270 bottom value="0 Ω"
R251 "ERJ-1GN0R00C" 0201#1 2141.26,1947.58 r270 bottom value="0 Ω"
R252 "ERJ-1GN0R00C" 0201#1 2141.26,1925.53 r90 bottom value="0 Ω"
R253 "ERJ-1GN0R00C" 0201#1 2230.23,1936.55 r0 bottom value="0 Ω"
SW1 "500ASSP1M2QE" 500ASSP1M2QE 1091.4,302.12 r270 top
SW2 "cmp00353" 450301014042 110.07,988.8 r270 top
SW3 "cmp00353" 450301014042 110.07,1868.8 r270 top
T1 "BAL-0032SSG" BAL-0032SSG 3587.48,1503.7 r90 top
T2 "TCBT-203+" GU1414-4 4285.02,787.05 r270 top
T3 "MTX2-183+" DG3006 4116.51,412.56 r180 top
T4 "TCBT-203+" GU1414-4 4072.01,787.05 r270 top
T5 "MABA-011108" MABA-011108 4331.48,444.93 r270 bottom
T6 "TCBT-203+" GU1414-4 4261.01,1936.89 r90 top
T7 "MTX2-183+" DG3006 4216.51,2311.24 r0 top
T8 "TCBT-203+" GU1414-4 4047.99,1936.89 r90 top
T9 "MABA-011108" MABA-011108 4040.52,2317.62 r90 bottom
TP1 "5010" Keystone5010 788.64,651.8 r0 top
TP2 "5125" Keystone5125 468.92,704.59 r0 top
U1 "DAC39RF20ANH" ANH0289A 4261,1361.97 r180 top locked
U2 "TPS259261DRC" DRC0010J 1203.81,357.32 r90 bottom
U3 "TPS82140SILR" SIL0008D 1055.09,686.29 r90 bottom
U4 "TPS70950DBV" DBV0005A 4819.58,362.49 r180 bottom
U5 "TMUX1108RSVR" RSV0016A 2620.92,917.76 r90 bottom
U6 "TMUX1108RSVR" RSV0016A 2470.91,752.01 r0 bottom
U7 "ADS1119IRTET" RTE0016D 2433.51,939.42 r180 bottom
U8 "TCA6408ARSVR" RSV0016A 2613.84,779.59 r90 bottom
U9 "INA180B1IDBVR" DBV0005A 1051.42,1521.43 r90 top
U10 "TPSM5D1806RDB" RDB0051A 474.1,1376.59 r270 bottom
U11 "TPS0401A-10DCK" DCK0006A 125.47,1331.34 r0 bottom
U12 "TPS0401B-10DCK" DCK0006A 126.1,1445.34 r0 bottom
U13 "TPSM82913RDU" RDU0028A 583.93,994.42 r270 bottom
U14 "TPSM82913RDU" RDU0028A 583.93,1785.94 r270 bottom
U15 "INA180B1IDBVR" DBV0005A 1925.82,313.21 r0 top
U16 "TPS7A9601DSC" DRC0010J 1633.7,369.31 r0 bottom
U17 "SN74AUP1G04DCK" DCK0005A 1066.93,1092.46 r270 bottom
U18 "LM27762DSS" DSS0012B 1183.7,1113.21 r270 bottom
U19 "OPA2387DGKR" DGK0008A 1202.17,950.49 r180 bottom
U20 "INA293B1IDBVR" DBV0005A 1326.19,1261.8 r270 bottom
U21 "SN74AUP1G08DCKT" DCK0005A 1499.13,1296.92 r0 bottom
U22 "SN74AUP1G04DCK" DCK0005A 1223.71,1727.94 r90 bottom
U23 "LM27762DSS" DSS0012B 1338.51,1607.23 r270 bottom
U24 "OPA2387DGKR" DGK0008A 1356.99,1444.51 r180 bottom
U25 "INA293B1IDBVR" DBV0005A 1481,1755.81 r270 bottom
U26 "INA180B1IDBVR" DBV0005A 1826.57,643.65 r90 top
U27 "TPS7A9601DSC" DRC0010J 1560.33,605.86 r0 bottom
U28 "TPS0401A-10DCK" DCK0006A 1648.95,791.87 r270 bottom
U29 "TPS0401B-10DCK" DCK0006A 1748.95,791.87 r270 bottom
U30 "INA180B1IDBVR" DBV0005A 1826.57,1013.65 r90 top
U31 "TPS0401A-10DCK" DCK0006A 1648.96,1161.87 r270 bottom
U32 "TPS7A9601DSC" DRC0010J 1560.33,975.86 r0 bottom
U33 "TPS0401B-10DCK" DCK0006A 1748.95,1161.87 r270 bottom
U34 "INA180B1IDBVR" DBV0005A 1757.19,1698.83 r90 top
U35 "TPS7A9601DSC" DRC0010J 1701.09,1406.71 r90 bottom
U36 "SN74LVC2G125DCUT" DCU0008A 806.45,2257.04 r270 bottom
U37 "FT4232HL-REEL" LQFP64-MFG 767.08,2271.61 r0 top locked
U38 "SN74AVC4T774BQB" BQB0016A-MFG 1181.85,2300.35 r0 bottom
U39 "SN74AVC4T774BQB" BQB0016A-MFG 1181.85,2500.35 r0 bottom
U40 "93LC46B-I/ST" TSSOP-8 672.59,2275.55 r270 bottom
U41 "TLV70233DBV" DBV0005A 281.52,1999.98 r180 bottom
U42 "SN74AVCH2T45DCU" DCU0008A 1181.85,2640.94 r0 bottom
U43 "TMUX1136DGS" DQA0010A#1 1173.01,2127.4 r0 bottom
U44 "TCA9548ARGER" RGE0024M 2483.64,430.43 r270 bottom
U45 "SN74AVCH2T45DCU" DCU0008A 1910,1857.24 r0 bottom
U46 "SN74AVC4T774RSV" RSV0016A 1931.66,2059.7 r0 bottom
U47 "SN74AVC4T774BQB" BQB0016A-MFG 1652.36,2147.1 r90 bottom
U48 "SN74CBTLV3257DGV" RSV0016A 1655.24,2337.75 r180 bottom
U49 "SN74AVC4T774BQB" BQB0016A-MFG 1649.11,1922.2 r180 bottom
U50 "SN74LVC1G125DRL" DRL0005A 1465.16,2237.26 r180 bottom
U51 "SN74LVC1G125DRL" DRL0005A 1465.16,2157.26 r180 bottom
U52 "SN74CBTLV3257DGV" RSV0016A 1420.12,1975.35 r90 bottom
U53 "SN74AVC4T774BQB" BQB0016A-MFG 1181.85,1975.35 r0 bottom
U54 "LMK04828BISQ/NOPB" NKD0064A 2618.18,1545.83 r180 bottom
U55 "TMP451AIDQFR" DQF0008A 4870.58,2368.6 r90 bottom
U56 "ATS1005-3DB-FD-T05" SUSUMU_ATS1005 4223.02,651.34 r270 top
U57 "ATS1005-3DB-FD-T05" SUSUMU_ATS1005 4010,651.34 r270 top
U58 "ATS1005-3DB-FD-T05" SUSUMU_ATS1005 4323.02,2072.6 r90 top
U59 "ATS1005-3DB-FD-T05" SUSUMU_ATS1005 4110,2072.6 r90 top
U60 "TMUX1136DGS" DQA0010A#2 5744.03,278.48 r0 top
U61 "24LC64FT-I/MNY" TDFN8 5912.59,288.32 r180 top
Y1 "ABM3-12.000MHZ-D2Y-T" XTAL_ABM3 480.78,2576.02 r45 top

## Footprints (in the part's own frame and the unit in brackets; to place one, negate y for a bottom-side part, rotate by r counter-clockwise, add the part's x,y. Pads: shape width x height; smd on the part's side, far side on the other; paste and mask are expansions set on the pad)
0201#1 [mm] "Data from Kemet datasheet CC101_COM dated 7/28/11"
  rrect20% 0.36x0.32 smd mask+0.051: 1(-0.28,0) 2(0.28,0)
  body extent -0.31,-0.16 0.31,0.16, height 0.26
0201#2 [mm] "Data from Kemet datasheet CC101_COM dated 7/28/11"
  rect 0.36x0.32 smd mask+0.048: 1(-0.28,0) 2(0.28,0)
  body extent -0.31,-0.16 0.31,0.16, height 0.26
0201_cap [mm] "Data from Kemet datasheet CC101_COM dated 7/28/11"
  rrect20% 0.36x0.32 smd mask+0.051: 1(-0.28,0) 2(0.28,0)
  body extent -0.31,-0.16 0.31,0.16, height 0.26
0201L#1 [mm] "Data from Kemet datasheet CC101_COM dated 7/28/11"
  rect 0.36x0.32 smd mask+0.048: 1(-0.28,0) 2(0.28,0)
  body extent -0.31,-0.16 0.31,0.16, height 0.26
0201L#2 [mm] "Data from Kemet datasheet CC101_COM dated 7/28/11"
  rrect20% 0.56x0.52 smd mask+0.051: 1(-0.38,0) 2(0.38,0)
  body extent -0.3,-0.15 0.3,0.15, height 0.23
0402L#1 [mm] "0402 from SM-752 data"
  rrect20% 0.6x0.5 smd mask+0.051: 1(-0.5,0) 2(0.5,0)
  body extent -0.55,-0.3 0.55,0.3, height 0.6
0402L#2 [mm] "0402 from SM-752 data"
  rect 0.6x0.5 smd: 1(-0.5,0) 2(0.5,0)
  body extent -0.55,-0.3 0.55,0.3, height 0.6
0402L_cap#1 [mm] "0402 from SM-752 data"
  rrect20% 0.6x0.5 smd mask+0.051: 1(-0.5,0) 2(0.5,0)
  body extent -0.55,-0.3 0.55,0.3, height 0.6
0402L_cap#2 [mm] "0402 from SM-752 data"
  rect 0.6x0.5 smd: 1(-0.5,0) 2(0.5,0)
  body extent -0.55,-0.3 0.55,0.3, height 0.6
500ASSP1M2QE [mm]
  rect 1.635x1.635 hole 1.09: 1(-2.54,0)
  round 1.635 hole 1.09: 2(0,0) 3(2.54,0)
  silkscreen extent -5.08,-2.54 5.08,2.54, body extent -5.08,-2.54 5.08,2.54, height 13.32
0603L [mm] "0603 from SM-752 data"
  rrect20% 0.8x0.85 smd: 1(-0.7,0) 2(0.7,0)
  silkscreen extent -0.07,-0.33 0.07,0.33, body extent -0.87,-0.47 0.87,0.47, height 1
0603L_cap [mm] "0603 from SM-752 data"
  rrect20% 0.8x0.85 smd: 1(-0.7,0) 2(0.7,0)
  silkscreen extent -0.07,-0.33 0.07,0.33, body extent -0.87,-0.47 0.87,0.47, height 1
0805L [mm] "0805 from SM-752 data"
  rrect20% 1.1x1.4 smd: 1(-0.75,0) 2(0.75,0)
  body extent -1.1,-0.72 1.1,0.72, height 1.45
0805L_cap [mm] "0805 from SM-752 data"
  rrect20% 1.1x1.4 smd: 1(-0.75,0) 2(0.75,0)
  body extent -1.1,-0.72 1.1,0.72, height 1.45
1206L [mm] "1206 from SM-752 data"
  rrect20% 1.1x1.75 smd: 1(-1.35,0) 2(1.35,0)
  silkscreen extent -0.4,-0.77 0.4,0.77, body extent -1.7,-0.9 1.7,0.9, height 1.35
1206L_cap [mm] "1206 from SM-752 data"
  rrect20% 1.1x1.75 smd: 1(-1.35,0) 2(1.35,0)
  silkscreen extent -0.4,-0.77 0.4,0.77, body extent -1.7,-0.9 1.7,0.9, height 1.35
450301014042 [mm]
  round 1.65 hole 1.016: 1(0,0) 2(-2.54,0)
  rect 1.65x1.65 hole 1.016: 3(2.54,0)
  silkscreen extent -4.25,-1.3 4.25,1.3, body extent -4.98,-1.25 5.02,1.25, height 5.9
ANH0289A [mm] "RF7x BGA package"
  round 0.45 smd paste+0 mask+0: A1(-6.4,6.4) A2(-5.6,6.4) A3(-4.8,6.4) A4(-4,6.4) A5(-3.2,6.4) A6(-2.4,6.4) A7(-1.6,6.4) A8(-0.8,6.4) A9(0,6.4) A10(0.8,6.4) A11(1.6,6.4) A12(2.4,6.4) A13(3.2,6.4) A14(4,6.4) A15(4.8,6.4) A16(5.6,6.4) A17(6.4,6.4) B1(-6.4,5.6) B2(-5.6,5.6) B3(-4.8,5.6) B4(-4,5.6) B5(-3.2,5.6) B6(-2.4,5.6) B7(-1.6,5.6) B8(-0.8,5.6) B9(0,5.6) B10(0.8,5.6) B11(1.6,5.6) B12(2.4,5.6) B13(3.2,5.6) B14(4,5.6) B15(4.8,5.6) B16(5.6,5.6) B17(6.4,5.6) C1(-6.4,4.8) C2(-5.6,4.8) C3(-4.8,4.8) C4(-4,4.8) C5(-3.2,4.8) C6(-2.4,4.8) C7(-1.6,4.8) C8(-0.8,4.8) C9(0,4.8) C10(0.8,4.8) C11(1.6,4.8) C12(2.4,4.8) C13(3.2,4.8) C14(4,4.8) C15(4.8,4.8) C16(5.6,4.8) C17(6.4,4.8) D1(-6.4,4) D2(-5.6,4) D3(-4.8,4) D4(-4,4) D5(-3.2,4) D6(-2.4,4) D7(-1.6,4) D8(-0.8,4) D9(0,4) D10(0.8,4) D11(1.6,4) D12(2.4,4) D13(3.2,4) D14(4,4) D15(4.8,4) D16(5.6,4) D17(6.4,4) E1(-6.4,3.2) E2(-5.6,3.2) E3(-4.8,3.2) E4(-4,3.2) E5(-3.2,3.2) E6(-2.4,3.2) E7(-1.6,3.2) E8(-0.8,3.2) E9(0,3.2) E10(0.8,3.2) E11(1.6,3.2) E12(2.4,3.2) E13(3.2,3.2) E14(4,3.2) E15(4.8,3.2) E16(5.6,3.2) E17(6.4,3.2) F1(-6.4,2.4) F2(-5.6,2.4) F3(-4.8,2.4) F4(-4,2.4) F5(-3.2,2.4) F6(-2.4,2.4) F7(-1.6,2.4) F8(-0.8,2.4) F9(0,2.4) F10(0.8,2.4) F11(1.6,2.4) F12(2.4,2.4) F13(3.2,2.4) F14(4,2.4) F15(4.8,2.4) F16(5.6,2.4) F17(6.4,2.4) G1(-6.4,1.6) G2(-5.6,1.6) G3(-4.8,1.6) G4(-4,1.6) G5(-3.2,1.6) G6(-2.4,1.6) G7(-1.6,1.6) G8(-0.8,1.6) G9(0,1.6) G10(0.8,1.6) G11(1.6,1.6) G12(2.4,1.6) G13(3.2,1.6) G14(4,1.6) G15(4.8,1.6) G16(5.6,1.6) G17(6.4,1.6) H1(-6.4,0.8) H2(-5.6,0.8) H3(-4.8,0.8) H4(-4,0.8) H5(-3.2,0.8) H6(-2.4,0.8) H7(-1.6,0.8) H8(-0.8,0.8) H9(0,0.8) H10(0.8,0.8) H11(1.6,0.8) H12(2.4,0.8) H13(3.2,0.8) H14(4,0.8) H15(4.8,0.8) H16(5.6,0.8) H17(6.4,0.8) J1(-6.4,0) J2(-5.6,0) J3(-4.8,0) J4(-4,0) J5(-3.2,0) J6(-2.4,0) J7(-1.6,0) J8(-0.8,0) J9(0,0) J10(0.8,0) J11(1.6,0) J12(2.4,0) J13(3.2,0) J14(4,0) J15(4.8,0) J16(5.6,0) J17(6.4,0) K1(-6.4,-0.8) K2(-5.6,-0.8) K3(-4.8,-0.8) K4(-4,-0.8) K5(-3.2,-0.8) K6(-2.4,-0.8) K7(-1.6,-0.8) K8(-0.8,-0.8) K9(0,-0.8) K10(0.8,-0.8) K11(1.6,-0.8) K12(2.4,-0.8) K13(3.2,-0.8) K14(4,-0.8) K15(4.8,-0.8) K16(5.6,-0.8) K17(6.4,-0.8) L1(-6.4,-1.6) L2(-5.6,-1.6) L3(-4.8,-1.6) L4(-4,-1.6) L5(-3.2,-1.6) L6(-2.4,-1.6) L7(-1.6,-1.6) L8(-0.8,-1.6) L9(0,-1.6) L10(0.8,-1.6) L11(1.6,-1.6) L12(2.4,-1.6) L13(3.2,-1.6) L14(4,-1.6) L15(4.8,-1.6) L16(5.6,-1.6) L17(6.4,-1.6) M1(-6.4,-2.4) M2(-5.6,-2.4) M3(-4.8,-2.4) M4(-4,-2.4) M5(-3.2,-2.4) M6(-2.4,-2.4) M7(-1.6,-2.4) M8(-0.8,-2.4) M9(0,-2.4) M10(0.8,-2.4) M11(1.6,-2.4) M12(2.4,-2.4) M13(3.2,-2.4) M14(4,-2.4) M15(4.8,-2.4) M16(5.6,-2.4) M17(6.4,-2.4) N1(-6.4,-3.2) N2(-5.6,-3.2) N3(-4.8,-3.2) N4(-4,-3.2) N5(-3.2,-3.2) N6(-2.4,-3.2) N7(-1.6,-3.2) N8(-0.8,-3.2) N9(0,-3.2) N10(0.8,-3.2) N11(1.6,-3.2) N12(2.4,-3.2) N13(3.2,-3.2) N14(4,-3.2) N15(4.8,-3.2) N16(5.6,-3.2) N17(6.4,-3.2) P1(-6.4,-4) P2(-5.6,-4) P3(-4.8,-4) P4(-4,-4) P5(-3.2,-4) P6(-2.4,-4) P7(-1.6,-4) P8(-0.8,-4) P9(0,-4) P10(0.8,-4) P11(1.6,-4) P12(2.4,-4) P13(3.2,-4) P14(4,-4) P15(4.8,-4) P16(5.6,-4) P17(6.4,-4) R1(-6.4,-4.8) R2(-5.6,-4.8) R3(-4.8,-4.8) R4(-4,-4.8) R5(-3.2,-4.8) R6(-2.4,-4.8) R7(-1.6,-4.8) R8(-0.8,-4.8) R9(0,-4.8) R10(0.8,-4.8) R11(1.6,-4.8) R12(2.4,-4.8) R13(3.2,-4.8) R14(4,-4.8) R15(4.8,-4.8) R16(5.6,-4.8) R17(6.4,-4.8) T1(-6.4,-5.6) T2(-5.6,-5.6) T3(-4.8,-5.6) T4(-4,-5.6) T5(-3.2,-5.6) T6(-2.4,-5.6) T7(-1.6,-5.6) T8(-0.8,-5.6) T9(0,-5.6) T10(0.8,-5.6) T11(1.6,-5.6) T12(2.4,-5.6) T13(3.2,-5.6) T14(4,-5.6) T15(4.8,-5.6) T16(5.6,-5.6) T17(6.4,-5.6) U1(-6.4,-6.4) U2(-5.6,-6.4) U3(-4.8,-6.4) U4(-4,-6.4) U5(-3.2,-6.4) U6(-2.4,-6.4) U7(-1.6,-6.4) U8(-0.8,-6.4) U9(0,-6.4) U10(0.8,-6.4) U11(1.6,-6.4) U12(2.4,-6.4) U13(3.2,-6.4) U14(4,-6.4) U15(4.8,-6.4) U16(5.6,-6.4) U17(6.4,-6.4)
  silkscreen extent -7.75,-7 7,7, body extent -6.9,-6.9 6.9,6.9, height 1.4
BAL-0032SSG [mil]
  round 1 smd mask+1.97: 1(45,165) 2(-45,-165) 3(45,-165)
  round 20 hole 10 mask+1.97: 4(-90,143) 4(-82,-165) 4(-77.04,-146.5) 4(-75,0) 4(-75,100) 4(-74.51,-98.77) 4(-66,143) 4(-63.5,-132.96) 4(-45,-128) 4(-42,143) 4(-26.5,-132.96) 4(-22,165) 4(-22,133) 4(-12.96,-146.5) 4(-8,-165) 4(0,100) 4(0,0) 4(0.49,-98.77) 4(8,165) 4(8,-165) 4(12.96,146.5) 4(12.96,-146.5) 4(26.5,132.96) 4(26.5,-132.96) 4(45,128) 4(45,-128) 4(63.5,132.96) 4(63.5,-132.96) 4(75,0) 4(75,100) 4(75.49,-98.77) 4(77.04,146.5) 4(77.04,-146.5) 4(82,165) 4(82,-165)
  round 1 smd paste-400 mask+1.97: 4(0,0)
  Top Layer region: -52,-185 -53.15,-184.77 -54.12,-184.12 -54.77,-183.15 -55,-182 -55,-182 -55,-165 -54.24,-161.17 -52.07,-157.93 -48.83,-155.76 -45,-155 -45,-155 -41.17,-155.76 -37.93,-157.93 -35.76,-161.17 -35,-165 -35,-165 -35,-182 -35.23,-183.15 -35.88,-184.12 -36.85,-184.77 -38,-185 -38,-185
  Top Layer region: 38,-185 36.85,-184.77 35.88,-184.12 35.23,-183.15 35,-182 35,-182 35,-165 35.76,-161.17 37.93,-157.93 41.17,-155.76 45,-155 45,-155 48.83,-155.76 52.07,-157.93 54.24,-161.17 55,-165 55,-165 55,-182 54.77,-183.15 54.12,-184.12 53.15,-184.77 52,-185 52,-185
  Top Layer region: 52,185 53.15,184.77 54.12,184.12 54.77,183.15 55,182 55,182 55,165 54.24,161.17 52.07,157.93 48.83,155.76 45,155 45,155 41.17,155.76 37.93,157.93 35.76,161.17 35,165 35,165 35,182 35.23,183.15 35.88,184.12 36.85,184.77 38,185 38,185
  Top Layer region: -100,175 -100,-175 -70,-175 -70,-165 -68.1,-155.43 -62.68,-147.32 -54.57,-141.9 -45,-140 -45,-140 -35.43,-141.9 -27.32,-147.32 -21.9,-155.43 -20,-165 -20,-165 -20,-175 20,-175 20,-165 21.9,-155.43 27.32,-147.32 35.43,-141.9 45,-140 45,-140 54.57,-141.9 62.68,-147.32 68.1,-155.43 70,-165 70,-165 70,-175 100,-175 100,175 70,175 70,165 68.1,155.43 62.68,147.32 54.57,141.9 45,140 45,140 35.43,141.9 27.32,147.32 21.9,155.43 20,165 20,165 20,175
  body extent -100,-175 100,175, height 110
BQB0016A-MFG [mm]
  rrect42% 0.24x0.6 smd paste+0 mask+0.07: 1(-0.25,1.65) 8(-0.25,-1.65) 9(0.25,-1.65) 16(0.25,1.65)
  rrect42% 0.6x0.24 smd paste+0 mask+0.07: 2(-1.15,1.25) 3(-1.15,0.75) 4(-1.15,0.25) 5(-1.15,-0.25) 6(-1.15,-0.75) 7(-1.15,-1.25) 10(1.15,-1.25) 11(1.15,-0.75) 12(1.15,-0.25) 13(1.15,0.25) 14(1.15,0.75) 15(1.15,1.25)
  round 0.454 hole 0.2 mask+0.05: 17(0,-0.75) 17(0,0.75)
  rrect10% 1x2 smd paste-1000 mask+0.07: 17(0,0)
  silkscreen extent -1.67,-1.8 1.3,1.8, body extent -1.25,-1.75 1.25,1.75, height 0.8
cbts130a [mm]
  round 5.5 hole 3.4 paste-2539.97 mask+0: ""(0,0)
  body extent -3.18,-2.75 3.18,2.75, height 2.09
CCS0603FLxLxx [mm]
  rrect33% 1.41x0.92 smd: 1(-0.9,0) 2(0.89,0)
  body extent -0.93,-0.52 0.93,0.52, height 0.66
CE_Mark_5mm [mil] "Minimum text height for CE Mark"
  silkscreen extent -138,-98 138,98
DBV0005A [mm] "SOT23, 5-Leads, Body 2.9x1.6mm, Pitch 0.95mm, Lead Span 2.8mm, IPC High Density"
  rrect18% 1.1x0.6 smd mask+0.07: 1(-1.3,0.95) 2(-1.3,0) 3(-1.3,-0.95) 4(1.3,-0.95) 5(1.3,0.95)
  silkscreen extent -0.35,-1.55 0.35,1.55, body extent -1.42,-1.46 1.42,1.46, height 1.09
DCK0005A [mm] "SOT353, 5-Leads, Body 2x1.3mm, Pitch 0.65mm, Lead Span 2.1mm, IPC High Density"
  rrect25% 0.9x0.4 smd mask+0.05: 1(-1.1,0.65) 2(-1.1,0) 3(-1.1,-0.65) 4(1.1,-0.65) 5(1.1,0.65)
  silkscreen extent -0.25,-1.1 0.25,1.1, body extent -1.14,-1 1.14,1, height 0.95
DCK0006A [mm] "SOT23, 6-Leads, Body 2x1.3mm, Pitch 0.65mm, Lead Span 2.1mm, IPC High Density"
  rrect25% 0.9x0.4 smd mask+0.05: 1(-1.1,0.65) 2(-1.1,0) 3(-1.1,-0.65) 4(1.1,-0.65) 5(1.1,0) 6(1.1,0.65)
  silkscreen extent -1.3,-1.07 0.55,1.1, body extent -1.14,-1 1.14,1, height 0.95
DCU0008A [mm] "TSSOP, 8-Leads, Body 2x2.3mm, Pitch 0.5mm, IPC High Density"
  rrect30% 0.8x0.3 smd mask+0.05: 1(-1.55,0.75) 2(-1.55,0.25) 3(-1.55,-0.25) 4(-1.55,-0.75) 5(1.55,-0.75) 6(1.55,-0.25) 7(1.55,0.25) 8(1.55,0.75)
  silkscreen extent -1.05,-1.05 0.38,1.05, body extent -1.56,-1 1.56,1, height 0.9
DG3006 [mm]
  rrect50% 0.3x1 smd mask+0.05: 1(-0.65,-1.55) 2(0,-1.55) 3(0.65,-1.55) 7(0.65,1.55) 8(0,1.55) 9(-0.65,1.55)
  rrect50% 1x0.3 smd mask+0.05: 4(2.05,-0.65) 5(2.05,0) 6(2.05,0.65) 10(-2.05,0.65) 11(-2.05,0) 12(-2.05,-0.65)
  round 0.025 smd mask+0.05: 13(0,0)
  Top Layer region: -1.008,-0.725 -1.225,-0.508 -1.225,0.725 1.225,0.725 1.225,-0.725
  silkscreen extent -2,-1.9 2,1.5, body extent -2,-1.5 2,1.5, height 0.9
DGK0008A [mm] "TSOP, 8-Leads, Body 3x3mm, Pitch 0.65mm, IPC Medium Density"
  rrect50% 1.45x0.45 smd mask+0.05: 1(-2.2,0.975) 2(-2.2,0.325) 3(-2.2,-0.325) 4(-2.2,-0.975) 5(2.2,-0.975) 6(2.2,-0.325) 7(2.2,0.325) 8(2.2,0.975)
  silkscreen extent -2.75,-1.55 0.95,1.55, body extent -2.45,-1.5 2.45,1.5, height 0.96
DQA0010A#1 [mm] "SON, 10-Leads, Body 1x2.5mm, Pitch 0.5mm, TI Recommended"
  rrect50% 0.565x0.2 smd mask+0.05: 1(-0.417,1) 2(-0.417,0.5) 4(-0.417,-0.5) 5(-0.417,-1) 6(0.417,-1) 7(0.417,-0.5) 9(0.417,0.5) 10(0.417,1)
  rrect28% 0.565x0.36 on Bottom Paste mask+0.07: 3(-0.417,0) 8(0.417,0)
  rrect25% 0.565x0.4 smd paste-0.2 mask+0.05: 3(-0.417,0) 8(0.417,0)
  silkscreen extent -0.67,-1.45 0.55,1.45, body extent -0.5,-1.25 0.5,1.25, height 0.55
DQA0010A#2 [mm] "SON, 10-Leads, Body 1x2.5mm, Pitch 0.5mm, TI Recommended"
  rrect50% 0.565x0.2 smd mask+0.07: 1(-0.417,1) 2(-0.417,0.5) 4(-0.417,-0.5) 5(-0.417,-1) 6(0.417,-1) 7(0.417,-0.5) 9(0.417,0.5) 10(0.417,1)
  rrect28% 0.565x0.36 on Top Paste mask+0.07: 3(-0.417,0) 8(0.417,0)
  rrect25% 0.565x0.4 smd paste-0.2 mask+0.07: 3(-0.417,0) 8(0.417,0)
  silkscreen extent -0.67,-1.45 0.55,1.45, body extent -0.5,-1.25 0.5,1.25, height 0.55
DQF0008A [mm] "SON-8"
  rrect40% 0.8x0.25 smd mask+0.05: 1(-0.8,0.75)
  rrect40% 0.7x0.25 smd mask+0.05: 2(-0.85,0.25) 3(-0.85,-0.25) 4(-0.85,-0.75) 5(0.85,-0.75) 6(0.85,-0.25) 7(0.85,0.25) 8(0.85,0.75)
  silkscreen extent -1.15,-1.17 0.38,1.17, body extent -1.05,-1.05 1.05,1.05, height 0.81
DQK0006C [mm] "WSON"
  rrect12% 0.9x0.86 on Bottom Paste: 0(0,0.325)
  rrect34% 0.7x0.29 on Bottom Paste: 0(0.095,-0.65)
  rrect33% 0.45x0.3 smd: 1(-0.975,0.65) 2(-0.975,0) 3(-0.975,-0.65) 4(0.975,-0.65) 5(0.975,0) 6(0.975,0.65)
  rrect33% 0.75x0.3 smd paste-0.15: 7(0.095,-0.65)
  rrect11% 1x0.95 smd paste-0.5: 8(0,0.325)
  silkscreen extent -1.15,-1.15 1.15,1.15, body extent -1,-1 1,1, height 0.75
DRC0010J [mm] "VSON-10"
  rrect42% 0.6x0.24 smd mask+0.07: 1(-1.4,1) 2(-1.4,0.5) 3(-1.4,0) 4(-1.4,-0.5) 5(-1.4,-1) 6(1.4,-1) 7(1.4,-0.5) 8(1.4,0) 9(1.4,0.5) 10(1.4,1)
  round 0.454 hole 0.2 mask+0.05: 11(-0.575,0) 11(0,-0.95) 11(0,0.95) 11(0.575,0)
  round 0.025 smd mask+0.07: 11(0,0)
  Top Layer region: -0.375,-1.65 -0.375,-1.2 -0.775,-1.2 -0.794,-1.196 -0.81,-1.185 -0.821,-1.169 -0.825,-1.15 -0.825,-1.15 -0.825,1.15 -0.821,1.169 -0.81,1.185 -0.794,1.196 -0.775,1.2 -0.775,1.2 -0.375,1.2 -0.375,1.65 -0.371,1.669 -0.36,1.685 -0.344,1.696 -0.325,1.7 -0.325,1.7 -0.325,1.7 -0.175,1.7 -0.175,1.7 -0.156,1.696 -0.14,1.685 -0.129,1.669 -0.125,1.65 -0.125,1.65 -0.125,1.2 0.125,1.2 0.125,1.65 0.129,1.669 0.14,1.685 0.156,1.696 0.175,1.7 0.175,1.7 0.175,1.7 0.325,1.7 0.325,1.7 0.344,1.696 0.36,1.685 0.371,1.669 0.375,1.65 0.375,1.65 0.375,1.2 0.775,1.2 0.794,1.196 0.81,1.185 0.821,1.169 0.825,1.15 0.825,1.15 0.825,-1.15 0.821,-1.169 0.81,-1.185 0.794,-1.196 0.775,-1.2 0.775,-1.2 0.375,-1.2 0.375,-1.65 0.371,-1.669 0.36,-1.685 0.344,-1.696 0.325,-1.7 0.325,-1.7 0.175,-1.7 0.156,-1.696 0.14,-1.685 0.129,-1.669 0.125,-1.65 0.125,-1.65 0.125,-1.2 -0.125,-1.2 -0.125,-1.65 -0.129,-1.669 -0.14,-1.685 -0.156,-1.696 -0.175,-1.7 -0.175,-1.7 -0.325,-1.7 -0.344,-1.696 -0.36,-1.685 -0.371,-1.669 -0.375,-1.65
  silkscreen extent -1.97,0.95 -1.84,1.08, body extent -1.5,-1.5 1.5,1.5, height 1
DRL0005A [mm] "SOTFL, 5-Flat Leads, Body 1.2x1.6x0.6mm, Pitch 0.5mm, TI recommended"
  rrect33% 0.67x0.3 smd mask+0.05: 1(-0.74,0.5) 2(-0.74,0) 3(-0.74,-0.5) 4(0.74,-0.5) 5(0.74,0.5)
  silkscreen extent -0.9,-0.95 0.5,0.95, body extent -0.8,-0.8 0.8,0.8, height 0.6
DSS0012B [mm] "WSON-10"
  rrect40% 0.5x0.25 smd mask+0.05: 1(-0.95,1.25) 2(-0.95,0.75) 3(-0.95,0.25) 4(-0.95,-0.25) 5(-0.95,-0.75) 6(-0.95,-1.25) 7(0.95,-1.25) 8(0.95,-0.75) 9(0.95,-0.25) 10(0.95,0.25) 11(0.95,0.75) 12(0.95,1.25)
  round 0.454 hole 0.2 mask+0.05: 13(0,-1.075) 13(0,1.075) 13(0,0)
  rrect11% 1x2.65 smd paste-0.5 mask+0.05: 13(0,0)
  silkscreen extent -1.3,1.63 -1.24,1.68, body extent -1,-1.5 1,1.5, height 0.8
ESD_Overlay_Small [mil]
  silkscreen extent -62,-48 64,61
FCC_disclaimer [mil]
FDL_Small [mil]
  silkscreen extent -54,-32 54,73
Fiducial10-20 [mm]
  round 1 smd paste-0.508 mask+0.203: 1(0,0)
FIL_BNX002-11 [mm]
  rect 1.8x1.8 hole 1.2: 1(2.5,2.5)
  round 1.8 hole 1.2: 2(2.5,-2.5) 3(-2.5,2.5) 4(-2.5,-2.5) 4(0,0) 4(5,0)
  silkscreen extent -6,-5.5 6,6.35, body extent -6,-5.5 6,5.5, height 13
FP-132134-15_CONN_SMA_JACK-MFG [mm]
  round 0.864 smd paste+0 mask+0: 1(0,0)
  round 2.6 hole 1.7 paste-2539.97 mask+0: 2(-2.54,2.54) 3(2.54,2.54) 4(-2.54,-2.54) 5(2.54,-2.54)
  silkscreen extent -3.6,-3.6 3.6,3.6, body extent -3.94,-3.94 3.94,3.94, height 0.25
FP-KRL3216T4A-M-R005-F-T1_1206-MFG [mm]
  rrect29% 1.15x0.35 smd paste+0 mask+0: 1(-0.775,1.5) 2(0.775,1.5)
  rrect9% 1.15x2.7 smd paste+0 mask+0: 3(-0.775,-0.325) 4(0.775,-0.325)
  silkscreen extent -1.97,-2.05 0.9,2.05, body extent -0.8,-1.45 0.8,1.75, height 0.7
FP-USB4105-GF-A_CONN_USB_9MM58_7MM53-MFG [mm]
  rrect100% 1x2.1 hole 1.7 slot 0.6 at 0 deg paste-2539.97 mask+0: 1(-4.32,3.015) 2(4.32,3.015)
  rrect100% 1x1.8 hole 1.4 slot 0.6 at 0 deg paste-2539.97 mask+0: 3(-4.32,-1.165) 4(4.32,-1.165)
  rrect17% 0.6x1.15 smd paste+0 mask+0: A1(-3.2,3.59) A4(-2.4,3.59) B1(3.2,3.59) B4(2.4,3.59)
  rrect33% 0.3x1.15 smd paste+0 mask+0: A5(-1.25,3.59) A6(-0.25,3.59) A7(0.25,3.59) A8(1.25,3.59) B5(1.75,3.59) B6(0.75,3.59) B7(-0.75,3.59) B8(-1.75,3.59)
  round 0.65 hole 0.65 unplated paste-2539.97 mask+0: ""(-2.89,2.515) ""(2.89,2.515)
  silkscreen extent -4.86,0.11 4.86,4.84, body extent -4.96,-3.94 4.96,4.27, height 0.25
GU1414-4 [mm]
  rrect30% 0.63x0.91 smd: 1(-1.345,-1.575) 2(1.345,-1.575) 4(-1.345,1.575)
  rrect20% 1.12x1.05 smd: 3(1.345,1.575)
  silkscreen extent -1.95,-1.95 -1.86,-1.86, body extent -1.91,-2.23 1.91,2.22, height 3.06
